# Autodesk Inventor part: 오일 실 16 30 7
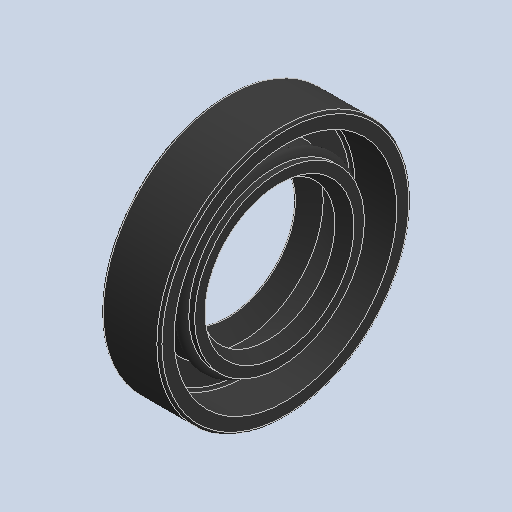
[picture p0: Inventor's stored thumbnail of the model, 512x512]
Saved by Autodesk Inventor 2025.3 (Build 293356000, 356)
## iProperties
Created: 2025-10
Part Number: 오일 실 16 30 7
Material: 고무
Description: 오일-실
Document SubType Name: Modeling
Designer: PC-15
Density: 0.93 g/cm^3
Appearance: 기본값
Author: jhkim
Sending System: Autodesk Inventor 2026
Preprocessor: ST-DEVELOPER v20.1
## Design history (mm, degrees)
feature "Solid1"
node "솔리드1"
